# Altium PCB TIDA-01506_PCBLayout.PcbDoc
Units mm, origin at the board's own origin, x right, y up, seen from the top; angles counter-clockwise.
Board outline 40 x 20 mm, 2 copper layers (Top Layer, Bottom Layer), stack 1.575 mm thick; 34 components, 16 nets, 81 pads, 25 vias.
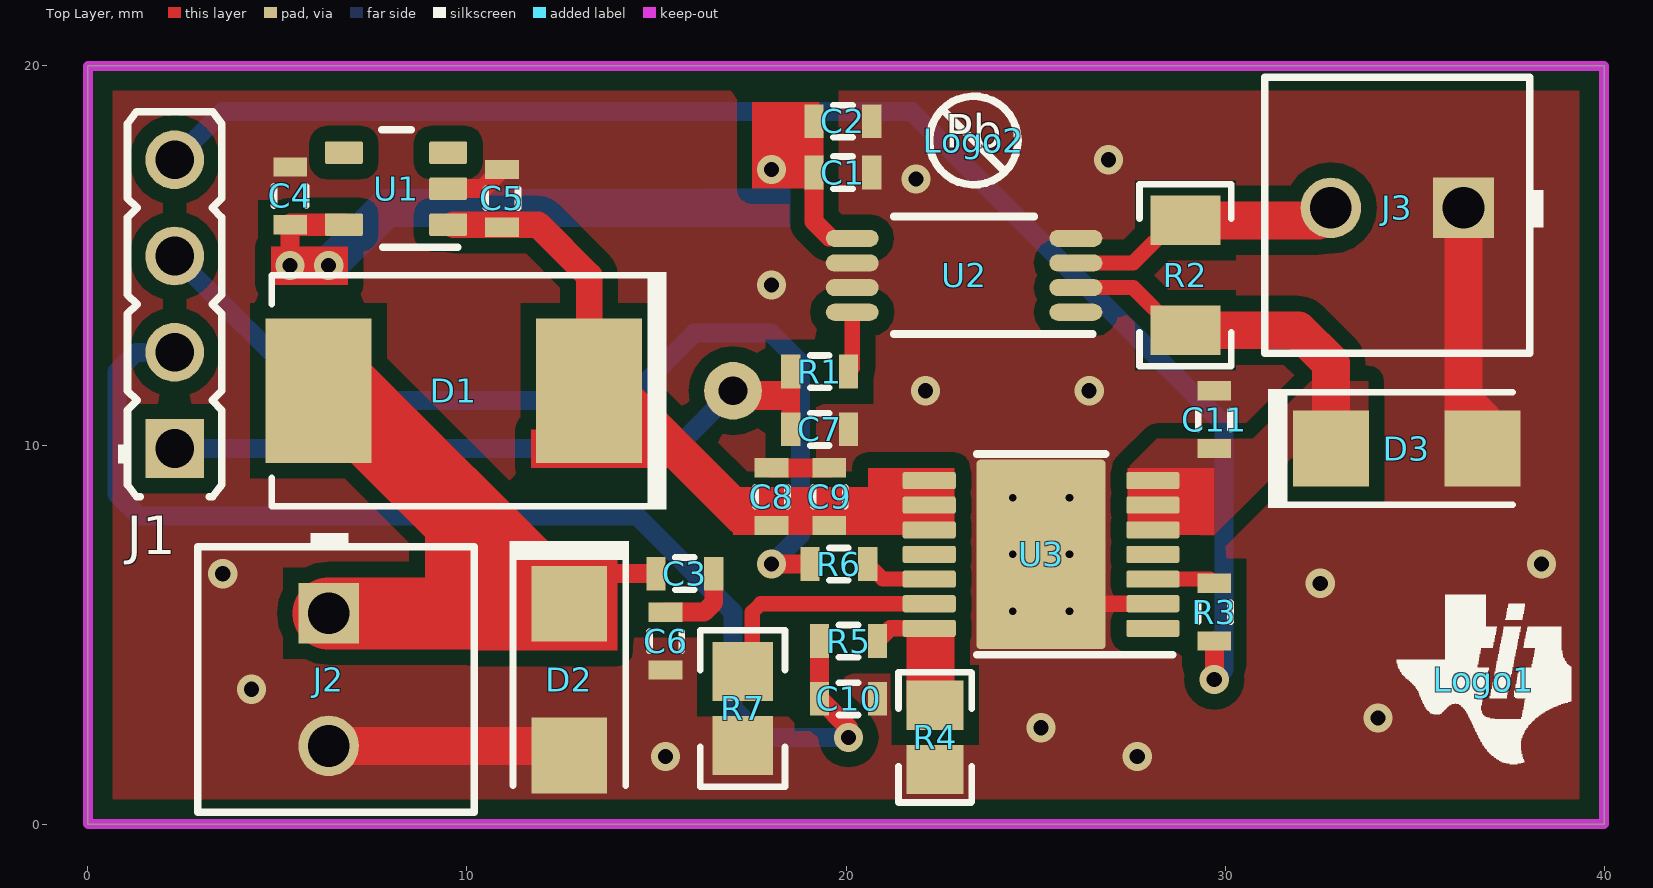
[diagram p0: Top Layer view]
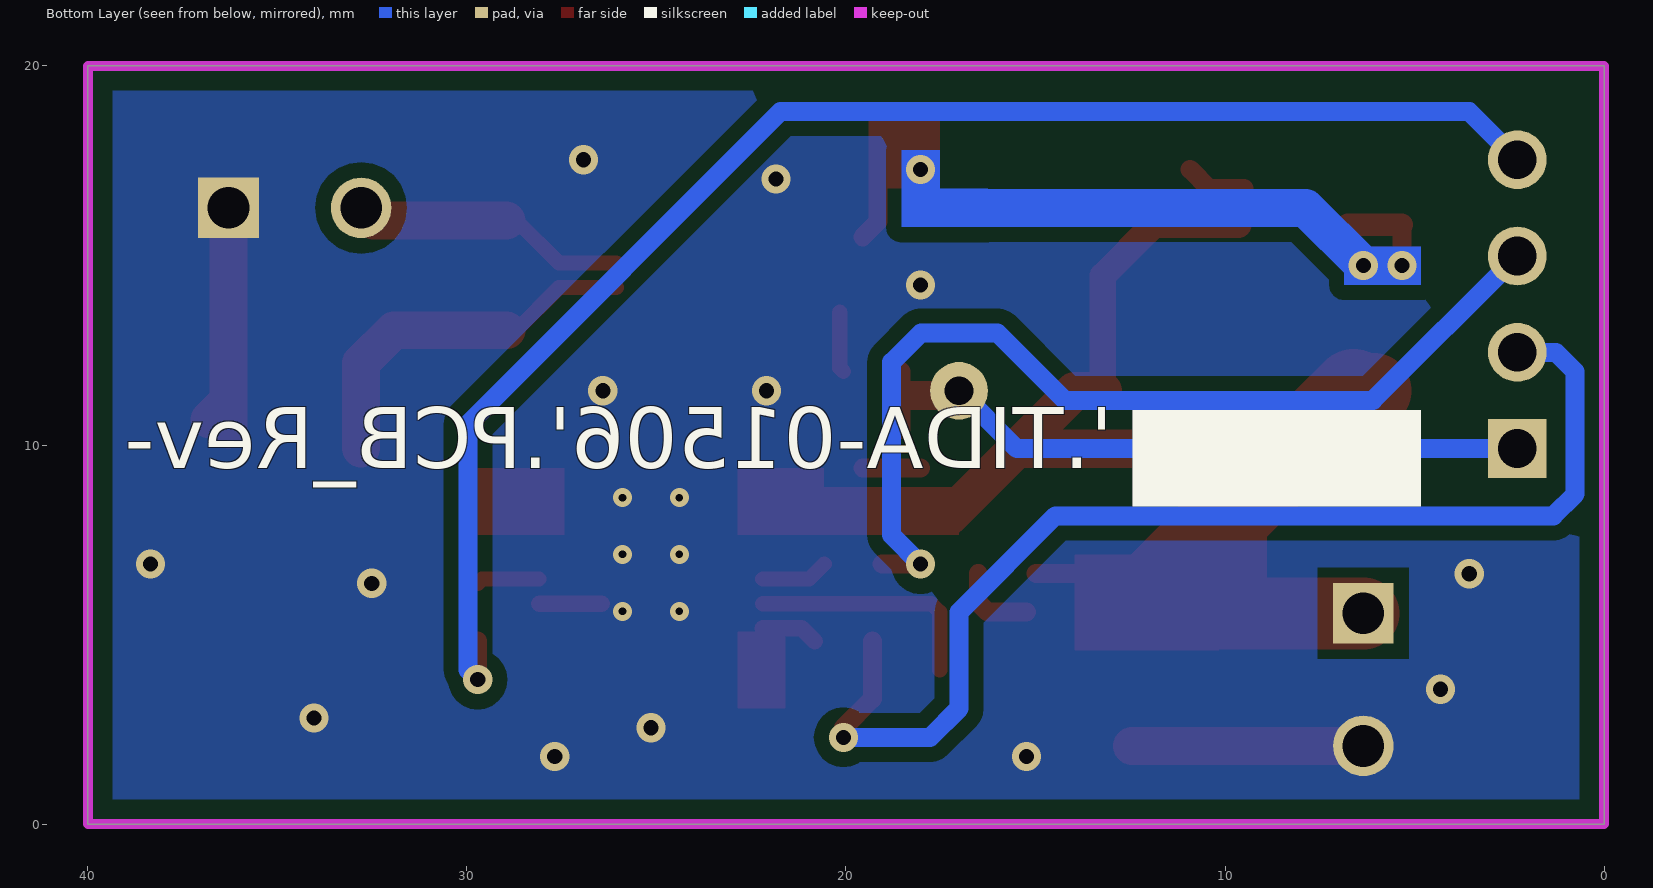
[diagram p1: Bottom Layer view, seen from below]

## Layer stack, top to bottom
Top Solder: solder mask 0.0102, Solder Resist, Dk 3.5
Top Layer: signal copper 0.0356
Dielectric1: core 1.5037, FR-4, Dk 4.8
Bottom Layer: signal copper 0.0356
Bottom Solder: solder mask 0.0102, Solder Resist, Dk 3.5

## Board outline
0,0 40,0 40,20 0,20

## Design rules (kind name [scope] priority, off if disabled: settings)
AcuteAngle [All] p1: minimum=4.50000000000000E+0001 checktracksonly=FALSE
AssemblyTestPointUsage [All] p1: valid=2
BoardOutlineClearance BoardOutlineClearance_MountingHoles [OnCopper and InComponentClass('Mounting Holes')] p1: gap=1.016 ignorepadtopadclearanceinfootprint=FALSE
BoardOutlineClearance BoardOutlineClearance_Poly [OnCopper and IsPoly] p2: gap=0.635 ignorepadtopadclearanceinfootprint=FALSE
BoardOutlineClearance [OnCopper and Not InComponentClass('Logo') and not InComponentClass('FiducialMark') and not InRegion(1000,500,4000,800) and not InPoly] p3: gap=0 ignorepadtopadclearanceinfootprint=FALSE
Clearance Clearance_Keepouts [((IsTrack Or IsArc) And Not InPoly) And IsFree and IsKeepOut vs ((IsTrack Or IsArc) And Not InPoly) And IsFree and IsKeepOut] p1: gap=0 ignorepadtopadclearanceinfootprint=FALSE
Clearance Clearance_Poly [InPolygon] p2: gap=0.4 ignorepadtopadclearanceinfootprint=FALSE except(0: Arc-Hole Track-Hole SMDPad-Hole THPad-Hole Via-Hole Fill-Hole Poly-Hole Region-Hole Text-Hole)
Clearance [All] p3: gap=0.2 ignorepadtopadclearanceinfootprint=FALSE except(0: Arc-Hole Track-Hole SMDPad-Hole THPad-Hole Via-Hole Fill-Hole Poly-Hole Region-Hole Text-Hole)
ComponentClearance ComponentClearance_MountingHoles_FiducialMarks [InComponentClass('Mounting Holes') vs InComponentClass('FiducialMark')] p1: gap=1.27 collisioncheckmode=3 verticalgap=0.254 showdistances=FALSE
ComponentClearance ComponentClearance_Shunt [InComponentClass('Header') vs InComponentClass('Shunt')] p2: gap=0 collisioncheckmode=3 verticalgap=0 showdistances=FALSE
ComponentClearance ComponentClearance_Logo [InComponentClass('Logo')] p3: gap=1.27 collisioncheckmode=3 verticalgap=0.254 showdistances=FALSE
ComponentClearance ComponentClearance_ScrewToNut [(HasFootprint('NY PMS 440 0025 PH')) vs (HasFootprint('Keystone_1902C'))] p4: gap=0.127 collisioncheckmode=3 verticalgap=0.254 showdistances=FALSE
ComponentClearance ComponentClearance_MountingHoles [InComponentClass('Mounting Holes')] p5: gap=6.35 collisioncheckmode=3 verticalgap=2540 showdistances=FALSE
ComponentClearance ComponentClearance_SmallPassives [HasFootprint('0201*') or HasFootprint('0402*') or HasFootprint('0508') or HasFootprint('0603*') or HasFootprint('0612') or HasFootprint('0805*') or HasFootprint('0815*') or HasFootprint('0830*') or HasFootprint('1206*') or HasFootprint('1210*') or HasFootprint('1808*') or HasFootprint('1812*') or HasFootprint('1825*') or HasFootprint('2010*') or HasFootprint('2220*') or HasFootprint('2225*') or HasFootprint('2512*') or HasFootprint('2728*') or HasFootprint('3518*') vs HasFootprint('0201*') or HasFootprint('0402*') or HasFootprint('0508') or HasFootprint('0603*') or HasFootprint('0612') or HasFootprint('0805*') or HasFootprint('0815*') or HasFootprint('0830*') or HasFootprint('1206*') or HasFootprint('1210*') or HasFootprint('1808*') or HasFootprint('1812*') or HasFootprint('1825*') or HasFootprint('2010*') or HasFootprint('2220*') or HasFootprint('2225*') or HasFootprint('2512*') or HasFootprint('2728*') or HasFootprint('3518*')] p6: gap=0.38 collisioncheckmode=3 verticalgap=0.254 showdistances=FALSE
ComponentClearance ComponentClearance_THtoSMT [IsThruComponent vs IsSMTComponent] p7: gap=1.016 collisioncheckmode=3 verticalgap=0.762 showdistances=FALSE
ComponentClearance ComponentClearance_THtoTH [IsThruComponent vs IsThruComponent] p8: gap=0.762 collisioncheckmode=3 verticalgap=0.762 showdistances=FALSE
ComponentClearance [All] p9: gap=0.762 collisioncheckmode=3 verticalgap=0.254 showdistances=FALSE
DiffPairsRouting [All] p1: maxlimit=2.54 minlimit=0.254 mostfreqgap=0.254 toplayer_minwidth=0.381 toplayer_maxwidth=0.381 toplayer_prefwidth=0.381 bottomlayer_minwidth=0.381 bottomlayer_maxwidth=0.381 bottomlayer_prefwidth=0.381 maxuncoupledlength=25.4
FabricationTestPointUsage TestPointUsage [All] p1: valid=2 allowmultiple=FALSE
FabricationTestpoint Testpoint [All] p1: side=3 testpointundercomponent=TRUE minsize=1.016 maxsize=2.54 preferedsize=1.524 minholesize=0 maxholesize=1.016 preferedholesize=0.813 testpointgrid=0.025 allowsidetop=TRUE allowsidebottom=TRUE usegrid=TRUE gridtolerance=0
FanoutControl Fanout_LCC [IsLCC] p1: bgadir=Out bgaviamode=Centered fanoutstyle=Auto fanoutdirection=Alternating viagrid=0.025 // Fanout_LCC (Default Rule)
FanoutControl Fanout_BGA [IsBGA] p2: bgadir=Out bgaviamode=Centered fanoutstyle=Auto fanoutdirection=Alternating viagrid=0.025 // Fanout_BGA (Default Rule)
FanoutControl Fanout_Default [All] p4: bgadir=Out bgaviamode=Centered fanoutstyle=Auto fanoutdirection=Alternating viagrid=0.025 // Fanout_Default (Default Rule)
FanoutControl Fanout_Small [(CompPinCount < 5)] p5: bgadir=Out bgaviamode=Centered fanoutstyle=Auto fanoutdirection=OutThenIn viagrid=0.025 // Fanout_Small (Default Rule)
HoleSize [All] p1: absolutevalues=TRUE maxlimit=6.375 minlimit=0.2 maxpercent=80.000 minpercent=20.000
MinimumAnnularRing MinimumAnnularRing_ThermalPadVias [IsVia and InAnyComponent] p1: minimumring=0
MinimumAnnularRing [All] p2: minimumring=0
MinimumSolderMaskSliver MinimumSolderMaskSliver_Logo [InComponentClass('Logo') vs InComponentClass('Logo')] p1: minsoldermaskwidth=0.018
MinimumSolderMaskSliver [All] p2: minsoldermaskwidth=0.1
PlaneConnect [All] p1: planeconnectstyle=Relief reliefexpansion=0.254 reliefentries=4 reliefconductorwidth=0.254 reliefairgap=0.254
PolygonConnect [All] p1: connectstyle=Direct reliefconductorwidth=0.254 reliefentries=4 polygonreliefangle="90 Angle" airgapwidth=0.254
RoutingVias ThermalPadVias [IsVia and InAnyComponent] p1: holewidth=0.2 width=0.5 viastyle="Through Hole" minholewidth=0.2 minwidth=0.5 maxholewidth=0.33 maxwidth=0.6
RoutingVias [All] p2: holewidth=0.406 width=0.864 viastyle="Through Hole" minholewidth=0.2 minwidth=0.66 maxholewidth=1.016 maxwidth=1.651
SilkToBoardRegionClearance [Not ((IsComment or IsDesignator) And (Hide <> 'False')) and not InRegion(1000,500,4000,800)] p1:
SilkToSilkClearance SilkToSilkClearance_Pb-FreeLogo [(HasFootprint('Pb-Free_Overlay_Medium') OR HasFootprint('Pb-Free_Overlay_Small')) vs (HasFootprint('Pb-Free_Overlay_Medium') OR HasFootprint('Pb-Free_Overlay_Small'))] p1: silktosilkclearance=0
SilkToSilkClearance [All] p2: silktosilkclearance=0
SilkToSolderMaskClearance SilkToComponentPadClearance [(IsPad or IsFill or IsRegion) and InAnycomponent] p1: minsilkscreentomaskgap=0 clearancetoexposedcopper=TRUE
SilkToSolderMaskClearance "Silk to Solder Mask Opening" [All] p2: minsilkscreentomaskgap=0 clearancetoexposedcopper=FALSE
SolderMaskExpansion [All] p1: expansion=0.05
Width [All] p1: maxlimit=2.54 minlimit=0.152 preferedwidth=0.254 checkconnectedcopper=TRUE
15 further rules are at their usual default settings.

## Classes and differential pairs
component class Header: J1
component class TIDA-01506_Schematics: C1 C2 C3 C4 C5 C6 C7 C8 C9 C10 C11 D1 D2 D3 D4 J1 J2 J3 R1 R2 R3 R4 R5 R6 R7 U1 U2 U3
component class AssemblyNote: ZZ1 ZZ2 ZZ3 ZZ4
component class EVM_Hardware: Logo1 Logo2 Logo3 ZZ1 ZZ2 ZZ3 ZZ4
component class Logo: Logo1

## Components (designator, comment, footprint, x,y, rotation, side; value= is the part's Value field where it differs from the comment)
C1 "0603YC104JAT2A" 0603S 19.92,17.189 r180 top value=0.1uF
C2 "CGA3E1X7R1V105K080AC" 0603S 19.92,18.542 r180 top value=1uF
C3 "GRM188R72A104KA35J" 0603S 15.748,6.604 r0 top value=0.1uF
C4 "GRM188Z71C225KE43" 0603S 5.334,16.57 r90 top value=2.2uF
C5 "CGA3E1X7R1V105K080AC" 0603S 10.922,16.51 r270 top value=1uF
C6 "GRM188R72A104KA35J" 0603S 15.24,4.826 r270 top value=0.1uF
C7 "0603YC104JAT2A" 0603S 19.304,10.414 r0 top value=0.1uF
C8 "0603YC104JAT2A" 0603S 18.034,8.636 r270 top value=0.1uF
C9 "CGA3E1X7R1V105K080AC" 0603S 19.558,8.636 r270 top value=1uF
C10 "CGA3E1X7R1V105K080AC" 0603S 20.066,3.302 r0 top value=1uF
C11 "CGA3E1X7R1V105K080AC" 0603S 29.718,10.668 r270 top value=1uF
D1 "B540C-13-F" SMC 9.652,11.43 r180 top value=40V
D2 "SM4T23AY" SMA 12.7,3.81 r270 top value=20V
D3 "B120-13-F" SMA 34.798,9.906 r0 top value=20V
J1 "0022284043" Molex_0022284043 2.286,13.716 r90 top
J2 "39357-0002" Molex_39357-0002 6.35,3.81 r270 top
J3 "39357-0002" Molex_39357-0002 34.544,16.256 r180 top
Logo1 "Texas Instruments" TI_Symbol_Overlay_Small 36.83,3.81 r0 top
Logo2 "Pb-Free Symbol" Pb-Free_Overlay_Small 23.368,18.034 r0 top
Logo3 "FCC disclaimer" FCC_disclaimer 59.69,85.852 r0 top
R1 "FC0603E50R0BTBST1" 0603S 19.304,11.938 r180 top value=50
R2 "UR73V2BTTDR100F" 1206 28.956,14.478 r270 top value=0.1
R3 "CRCW060310K0JNEA" 0603S 29.718,5.588 r270 top value=10k
R4 "CRCW0805750RJNEA" 0805 22.352,2.286 r270 top value=750
R5 "CRCW060310K0JNEA" 0603S 20.066,4.826 r0 top value=10k
R6 "CRCW060310K0JNEA" 0603S 19.812,6.858 r0 top value=10k
R7 "CRCW08051K00FKEA" 0805M 17.272,3.048 r90 top value=1.00k
U1 "TPS70950QDBVRQ1" DBV0005A_N 8.128,16.764 r180 top
U2 "INA240A1QPWRQ1" PW0008A_N 23.114,14.478 r180 top
U3 "TPS1H100AQPWPRQ1" PWP0014F_N 25.146,7.112 r180 top
ZZ1 "This Assembly Note is for PCB labels only" AssemblyNoteLabel 4.699,100.025 r0 top
ZZ2 "These assemblies are ESD sensitive, ESD precautions shall be observed." AssemblyNote 4.699,97.259 r0 top
ZZ3 "These assemblies must be clean and free from flux and all contaminants. Use of no clean flux is not acceptable." AssemblyNote 4.699,95.01 r0 top
ZZ4 "These assemblies must comply with workmanship standards IPC-A-610 Class 2, unless otherwise specified." AssemblyNote 4.699,92.761 r0 top

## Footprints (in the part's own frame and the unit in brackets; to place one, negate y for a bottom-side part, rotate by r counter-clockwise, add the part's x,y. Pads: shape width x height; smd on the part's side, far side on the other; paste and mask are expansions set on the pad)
0603S [mil]
  rect 20x35 smd: 1(-30,0) 2(30,0)
  silkscreen extent -10,-17 10,17, body extent -34,-19 34,19, height 39
0805 [mm] "0805 from SM-752 data"
  rect 1.3x1.5 smd: 1(-0.85,0) 2(0.85,0)
  silkscreen extent -1.72,-0.97 1.72,0.97, body extent -1.1,-0.72 1.1,0.72, height 1.45
0805M [mm] "0805 from SM-752 data"
  rect 1.55x1.6 smd: 1(-0.975,0) 2(0.975,0)
  silkscreen extent -2.07,-1.12 2.07,1.12, body extent -1.1,-0.72 1.1,0.72, height 1.45
1206 [mm] "1206 from SM-752 data"
  rect 1.3x1.85 smd: 1(-1.45,0) 2(1.45,0)
  silkscreen extent -2.4,-1.21 2.4,1.21, body extent -1.7,-0.9 1.7,0.9, height 1.35
AssemblyNote [mm] "Assembly Note"
AssemblyNoteLabel [mm] "Assembly Note for PCB Labels"
DBV0005A_N [mm] "SOT23, 5-Leads, Body 2.9x1.6mm, Pitch 0.95mm, Lead Span 2.8mm, IPC Medium Density"
  rrect17% 1x0.6 smd: 1(-1.375,0.95) 2(-1.375,0) 3(-1.375,-0.95) 4(1.375,-0.95) 5(1.375,0.95)
  silkscreen extent -1.63,-1.55 0.38,1.55, body extent -1.42,-1.46 1.42,1.46, height 1.09
FCC_disclaimer [mm]
Molex_39357-0002 [mm] "Terminal Block, 3.5 mm, 2x1, TH"
  rect 1.6x1.6 hole 1.1: 1(-1.75,0)
  round 1.6 hole 1.1: 2(1.75,0)
  silkscreen extent -3.86,-3.45 3.5,3.84, body extent -3.55,-3.45 3.56,3.84, height 8.51
Molex_0022284043 [mm] "Header, 2.54mm, 4x1, TH"
  rect 1.55x1.55 hole 1.02: 1(-3.81,0)
  round 1.55 hole 1.02: 2(-1.27,0) 3(1.27,0) 4(3.81,0)
  silkscreen extent -5.08,-1.24 5.08,1.5, body extent -5.08,-1.24 5.08,1.24, height 8.4
Pb-Free_Overlay_Small [mm]
  silkscreen extent -1.16,-1.17 1.17,1.17
PW0008A_N [mm] "TSOP, 8-Leads, Body 3x4.4mm, Pitch 0.65mm, IPC Medium Density"
  oval 1.4x0.45 smd: 1(-2.95,0.975) 2(-2.95,0.325) 3(-2.95,-0.325) 4(-2.95,-0.975) 5(2.95,-0.975) 6(2.95,-0.325) 7(2.95,0.325) 8(2.95,0.975)
  silkscreen extent -3.4,-1.55 1.85,1.55, body extent -3.21,-1.5 3.21,1.5, height 1.2
PWP0014F_N [mm] "TSOP, 14-Leads, Body 5x4.4mm, Pitch 0.65mm, Thermal Pad 3x3 mm, IPC Medium Density"
  rrect22% 1.4x0.45 smd: 1(-2.95,1.95) 2(-2.95,1.3) 3(-2.95,0.65) 4(-2.95,0) 5(-2.95,-0.65) 6(-2.95,-1.3) 7(-2.95,-1.95) 8(2.95,-1.95) 9(2.95,-1.3) 10(2.95,-0.65) 11(2.95,0) 12(2.95,0.65) 13(2.95,1.3) 14(2.95,1.95)
  rrect6% 3.4x5 smd paste-2 mask-2: 15(0,0)
  rrect4% 2.31x2.46 on Top Paste: 15(0,0)
  rrect4% 2.31x2.46 on Top Solder: 15(0,0)
  silkscreen extent -3.47,-2.65 1.7,2.65, body extent -3.21,-2.5 3.21,2.5, height 1
SMA [mm] "Molded Diode, 2-Leads, Body 4.3x2.6mm, IPC Medium Density, based on OnSemi component dimensions and land pattern"
  rect 2x2 smd: 1(-2,0) 2(2,0)
  silkscreen extent -3.66,-1.57 2.79,1.57, body extent -2.6,-1.3 2.6,1.3, height 2.42
SMC [mil] "Molded Diode, 2-Leads, Body 6.9x5.8mm, IPC Medium Density, based on OnSemi component dimensions and land patterns"
  rect 110x150 smd: 1(-140.49,0) 2(140.49,0)
  silkscreen extent -221,-124 189,123, body extent -156,-116 156,116, height 91
TI_Symbol_Overlay_Small [mm]
  silkscreen extent -2.3,-2.23 2.3,2.24

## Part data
C1 C7 C8: "CAP, CERM, 0.1 µF, 16 V, +/- 5%, X7R, 0603", Cap_Case=0603, Manufacturer=AVX, Supplier Part Number 1=478-3726-1-ND, TempCo=X7R, Tolerance_%=5, Value1="0.039 ohm", Value2=16V, ValueDisplayed=0.1µF
C2 C9 C10 C11: "CAP, CERM, 1 µF, 35 V, +/- 10%, X7R, AEC-Q200 Grade 1, 0603", Cap_Case=0603, Manufacturer=TDK, Supplier Part Number 1=445-174215-1-ND, TempCo=X7R, Tolerance_%=10, Value1="0.005522 ohm", Value2=35V, ValueDisplayed=22nf
C3 C6: "CAP, CERM, 0.1 µF, 100 V, +/- 10%, X7R, 0603", Cap_Case=0603, Manufacturer=MuRata, Supplier Part Number 1=490-6439-1-ND, TempCo=X7R, Tolerance_%=10, Value1=Unknown, Value2=100V, ValueDisplayed=0.1µF
C4: "CAP, CERM, 2.2 µF, 16 V, +/- 10%, X7R, 0603", Cap_Case=0603, Manufacturer=MuRata, Supplier Part Number 1=81-GRM188Z71C225KE3D, TempCo=X7R, Tolerance_%=10, Value1=Unknown, Value2=16V, ValueDisplayed=2.2µF
C5: "CAP, CERM, 1 µF, 35 V, +/- 10%, X7R, AEC-Q200 Grade 1, 0603", Cap_Case=0603, Manufacturer=TDK, Supplier Part Number 1=445-174215-1-ND, TempCo=X7R, Tolerance_%=10, Value1="0.005522 ohm", Value2=35V, ValueDisplayed=1µF
D1: "Diode, Schottky, 40 V, 5 A, SMC", Manufacturer="Diodes Inc.", Supplier Part Number 1=B540C-FDICT-ND, Value1=5A, Value2=0.55V
D2: library part CMP-0078853-1, "Diode, TVS, Uni, 20 V, 42.8 Vc, AEC-Q101, SMA", Manufacturer=STMicroelectronics, Supplier Part Number 1=497-10912-2-ND
D3: "Diode, Schottky, 20 V, 1 A, SMA", Manufacturer="Diodes Inc.", Supplier Part Number 1=B120-FDICT-ND, Value1=1A, Value2=0.5V
J1: "Header, 2.54mm, 4x1, Tin, TH", Color=Black, Current_A=4, Manufacturer=Molex, Supplier Part Number 1=WM50016-04-ND, Voltage_V=250
J2 J3: "Terminal Block, 3.5 mm, 2x1, Tin, TH", Manufacturer=Molex, Supplier Part Number 1=WM7877-ND
Logo1: library part TI_Logo, "Texas Instrument Corporate Signature"
Logo2: library part Pb-Free
Logo3: library part FCC_disclaimer, "FCC_disclaimer"
R1: "RES, 50, 0.1%, 0.125 W, 0603", Manufacturer="Vishay Thin Film", Power_W=0.125, Supplier Part Number 1=FC0603-50BFCT-ND, TempCo="25 ppm/C", Tolerance_%=0.1, Value1=0.1%, Value2=0.125W, Value_Code=50R0, ValueDisplayed=50
R2: library part CMP-0074897-1, "RES, 0.1, 1%, 0.5 W, AEC-Q200 Grade 1, 1206", Manufacturer="KOA Speer", Power_W=500mW, Supplier Part Number 1=660-UR73V2BTTDR100F, TempCo="100 ppm/C", Tolerance_%=1%, Value2=0.5W, Value_Code=R100, ValueDisplayed=0.1
R3 R5 R6: "RES, 10 k, 5%, 0.1 W, 0603", Manufacturer=Vishay-Dale, Power_W=0.1, Supplier Part Number 1=541-10KGCT-ND, TempCo="200 ppm/C", Tolerance_%=5, Value1=5%, Value2=0.1W, Value_Code=10k0, ValueDisplayed=10k
R4: "RES, 750, 5%, 0.125 W, 0805", Manufacturer=Vishay-Dale, Power_W=0.125, Supplier Part Number 1=541-750ACT-ND, TempCo="200 ppm/C", Tolerance_%=5, Value1=5%, Value2=0.125W, Value_Code=750R, ValueDisplayed=750
R7: "RES, 1.00 k, 1%, 0.125 W, 0805", Manufacturer=Vishay-Dale, Power_W=0.125, Supplier Part Number 1=541-1.00KCCT-ND, TempCo="100 ppm/C", Tolerance_%=1, Value1=1%, Value2=0.125W, Value_Code=1k00, ValueDisplayed=1.00k
U1: library part CMP-0079136-1, "150-mA, 30-V, Ultra-Low IQ, Wide Input LDO with Reverse Current Protection for Automotive, DBV0005A (SOT-23-5)", Alternate Manufacturer="Texas Instruments"
U2: library part CMP-0077375-1, "Automotive, Wide Common-Mode Range, High- and Low-Side, Bidirectional, Zero-Drift, Current-Sense Amplifier With Enhanced PWM Rejection, PW0008A (TSSOP-8)", Alternate Manufacturer="Texas Instruments"
U3: "40V/100mOhm Single Channel Smart High Side Switch, PWP0014F (TSSOP-14)", Alternate Manufacturer="Texas Instruments"
ZZ1: library part AssemblyNoteLabel
ZZ2 ZZ3 ZZ4: library part AssemblyNote

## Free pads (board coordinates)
  round 1.524 hole 0.762: 2(17.018,11.43)

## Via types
v1: diameter 0.77, hole 0.4, Top Layer to Bottom Layer, 19 vias
v2: diameter 0.5, hole 0.2, Top Layer to Bottom Layer, tented both sides, 4 vias
v3: diameter 0.5, hole 0.2, Top Layer to Bottom Layer, 2 vias

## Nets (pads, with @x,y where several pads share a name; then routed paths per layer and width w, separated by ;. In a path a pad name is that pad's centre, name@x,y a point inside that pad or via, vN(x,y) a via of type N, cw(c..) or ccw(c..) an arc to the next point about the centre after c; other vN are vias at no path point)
5V: C1.2 C2.2 C4.1 U1.5 U2.5 | length 16.8
  Top Layer w0.5: v1(5.334,14.732) C4.1 C4.1@5.34,15.814 ; C2.2 C1.2 19.158,15.894 U2.5@19.558,15.494
  Top Layer w0.6: C4.1@5.34,15.814 U1.5
  Bottom Layer w1: v1(6.35,14.732) 7.874,16.256 16.764,16.256
  other v1: 18.034,17.272
12V: C3.1 D1.2 D2.1 J2.1 | length 15.8
  Top Layer w0.5: D2.1@13.494,6.604 C3.1
  Top Layer w1.9: J2.1 11.684,5.56
  Top Layer w2: D1.2 D1.2@6.604,11.43
  Top Layer w2.2: D1.2@6.604,11.43 12.224,5.81 D2.1
GND: C1.1 C2.1 C4.2 C5.1 C6.2 C7.2 C8.1 C9.1 C10.2 C11.1 D2.2 D3.2 J2.2 J3.1 R4.2 R7.1 U1.2 U2.4 U2.6 U2.7 U3.2 U3.15@25.146,7.112 | length 17.5
  Top Layer w0.44: U3.15@26.446,5.812 U3.2
  Top Layer w0.5: U1.2 10.414,16.764 C5.1 ; C8.1 C9.1
  Top Layer w1: J2.2 D2.2@12.45,2.06 ; D3.2@36.294,10.41 J3.1 ; 36.294,11.172 D3.2@36.798,10.668
  other v1: 15.24,1.778 27.686,1.778 25.146,2.54 34.036,2.794 4.318,3.556 32.512,6.35 3.556,6.604 38.354,6.858 22.098,11.43 26.416,11.43 18.034,14.224 21.844,17.018 26.924,17.526
  other v2: 24.396,5.612 25.896,5.612 24.396,8.612 25.896,8.612
  other v3: 24.396,7.112 25.896,7.112
INAOUTTOMCU2.4: C7.1 J1.1 pad.2 R1.2 | length 17.1
  Top Layer w0.5: C7.1@18.542,10.668 C7.1 R1.2
  Bottom Layer w0.5: J1.1 15.494,9.906 pad.2
NetC3_2: C3.2 C6.1 | length 2.1
  Top Layer w0.5: C6.1 16.256,5.588 16.51,5.842 C3.2
NetR1_1: R1.1 U2.8 | length 1.6
  Top Layer w0.4: R1.1 20.164,12.036 U2.8
NetR3_1: R3.1 U3.3 | length 1.7
  Top Layer w0.4: U3.3 29.606,6.462 R3.1
NetR4_1: R4.1 R5.2 U3.14 | length 1.5
  Top Layer w0.44: R5.2 21.164,5.162 U3.14
NetR6_2: R6.2 U3.12 | length 1.8
  Top Layer w0.4: R6.2 20.97,6.462 U3.12
NetR7_2: R7.2 U3.13 | length 6.3
  Top Layer w0.4: R7.2@17.526,4.064 17.526,5.588 17.75,5.812 U3.13
OUT_SWITCH: C11.2 D3.1 R2.2 U2.2 U3.5 U3.6 U3.7 | length 9.6
  Top Layer w0.4: U2.2 27.577,14.153 R2.2@28.702,13.028
  Top Layer w1: R2.2 31.93,13.028 32.798,12.16 D3.1
P2.5_PWM: J1.4 R3.2 | length 39.5
  Top Layer w0.5: v1(29.718,3.81) R3.2
  Bottom Layer w0.5: J1.4 3.556,18.796 21.73,18.796 29.972,10.554 29.972,4.064 v1(29.718,3.81)
P2.6_HS_SWITCH_CS: C10.1 J1.2 R5.1 | length 31.3
  Top Layer w0.5: R5.1 C10.1 20.066,2.54 v1(20.066,2.286)
  Bottom Layer w0.5: J1.2 1.27,12.446 0.762,11.938 0.762,8.705 1.337,8.13 14.476,8.13 17.018,5.588 17.018,3.048 17.78,2.286 v1(20.066,2.286) v1@20.066,2.25
P8.1_DIAG_EN: J1.3 R6.1 | length 25.8
  Top Layer w0.5: v1(18.034,6.858) R6.1
  Bottom Layer w0.5: J1.3 6.096,11.176 14.224,11.176 16.002,12.954 18.026,12.954 18.796,12.184 18.796,7.62 v1(18.034,6.858)
SOLENOID_1: J3.2 R2.1 U2.3 | length 7.1
  Top Layer w0.4: U2.3 27.577,14.803 R2.1@28.702,15.928
  Top Layer w1: R2.1 32.466,15.928 J3.2
VCC_12V: C5.2 C8.2 C9.2 D1.1 U1.1 U3.8 U3.9 U3.10 | length 12.6
  Top Layer w0.7: U1.1@9.652,15.814 11.872,15.814 13.221,14.465 D1.1
  Top Layer w1.003: D1.1 13.97,11.43 17.272,8.128
pads on no net: U1.3 U1.4 U2.1 U3.1 U3.4 U3.11 U3.15@25.146,7.112

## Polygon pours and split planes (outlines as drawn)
OUT_SWITCH on Top Layer "TOP_LAYER_OUT_SWITCH_P002" (solid, remove dead copper, pour order 2): 27.432,9.398 28.194,10.16 29.218,10.16 30.734,10.16 32.258,11.684 33.782,11.684 33.782,9.652 31.75,9.652 29.718,7.62 29.21,7.62 28.702,7.62
GND on Top Layer "TOP_LAYER_GND_P016" (solid, remove dead copper, pour order 16): 0,20.066 40.132,20.066 40.132,0 0,0
GND on Bottom Layer "BOTTOM_LAYER_GND_P014" (solid, remove dead copper, pour order 14): 0,20.066 40.132,20.066 40.132,0.254 39.878,0 0,0

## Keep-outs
Keep-Out Layer:
  the board outline again, w0.254
  text ".Layer_Name" at 14.656,-21.806 h1.52

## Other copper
Top Layer:
  rectangle net OUT_SWITCH: 27.432,7.62 29.718,9.398
  rectangle net VCC_12V: 20.574,7.62 22.86,9.398
  region net 5V: 19.304,16.764 19.304,19.05 17.526,19.05 17.526,16.764
  rectangle net NetR4_1: 21.59,3.048 22.86,5.08
  rectangle net 12V: 10.16,4.572 13.97,7.112
  rectangle net VCC_12V: 17.018,7.62 20.828,8.89
  rectangle net VCC_12V: 11.684,9.398 15.494,10.414
  region net 5V: 6.858,14.224 6.858,15.24 4.826,15.24 4.826,14.224
  rectangle net 12V: 8.89,5.56 11.176,8.128
  rectangle net INAOUTTOMCU2.4: 17.018,10.922 18.542,11.684
  text ".Layer_Name" at 14.656,-21.806 h1.52
Bottom Layer:
  rectangle net 5V: 16.256,15.748 18.288,16.764
  rectangle net 5V: 17.526,15.748 18.542,17.78
  region net 5V: 6.858,14.224 6.858,15.24 4.826,15.24 4.826,14.224
  text ".Layer_Name" at 14.656,-21.806 h1.52

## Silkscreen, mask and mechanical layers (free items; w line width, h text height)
Top Overlay:
  text ".Layer_Name" at 14.656,-21.806 h1.52
Bottom Overlay:
  region: 12.446,10.922 4.826,10.922 4.826,8.382 12.446,8.382
  text "'.TIDA-01506'.PCB_Rev-" at 12.954,8.865 h2.75
  text ".Layer_Name" at 14.656,-21.806 h1.52
Top Paste:
  text ".Layer_Name" at 14.656,-21.806 h1.52
Bottom Paste:
  text ".Layer_Name" at 14.656,-21.806 h1.52
Top Solder:
  text ".Layer_Name" at 14.656,-21.806 h1.52
  text ".Layer_Name" at 14.656,-21.806 h1.52
Bottom Solder:
  text ".Layer_Name" at 14.656,-21.806 h1.52
Drill Guide:
  text ".Layer_Name" at 14.656,-21.806 h1.52
M1 Board Outline:
  the board outline again, w0.254
  text ".Layer_Name" at 14.656,-21.806 h1.52
M2 Board Dimensions:
  rectangle: 3.175,-10.16 12.7,-6.985
  rectangle: 0,-6.985 3.175,-3.81
  lines w0.178: 0,-6.985 25.4,-6.985 ; 3.175,-10.16 3.175,-3.81 ; 6.35,-10.16 6.35,-3.81 ; 12.7,-10.16 12.7,-3.81 ; 19.05,-10.16 19.05,-3.81 ; 0,-10.16 0,-3.81 25.4,-3.81 25.4,-10.16 0,-10.16
  text ".Layer_Name" at 14.656,-21.806 h1.52
M3 3D STEP Top:
  text ".Layer_Name" at 14.656,-21.806 h1.52
M4 3D STEP Bottom:
  text ".Layer_Name" at 14.656,-21.806 h1.52
M5 Assembly Top:
  lines w0.254: -7.417,-23.626 160.223,-23.626 ; -7.417,-18.462 160.274,-18.462 ; -7.417,-13.297 -7.417,-28.791 94.31,-28.791 160.274,-28.791 160.274,-13.297 -7.404,-13.297 -7.404,-28.791 32.614,-28.791 ; 55.194,-28.791 55.194,-13.297 ; 87.376,-18.462 87.376,-13.297 ; 108.712,-18.462 108.712,-13.297 ; 124.511,-28.956 124.511,-23.804
  text "COMPONENTS MARKED 'DNP' SHOULD NOT BE POPULATED." at 29.299,-8.09 h1.52
  text "ASSEMBLY VARIANT:" at 29.286,-11.024 h1.52
  text ".VariantName" at 55.601,-11.024 h1.52
  text "PCB VIEWED FROM TOP SIDE" at -5.804,-16.654 h1.52
  text "BOARD #:" at 57.099,-16.654 h1.52
  text ".PRJ_Number" at 70.955,-16.654 h1.52
  text "REV:" at 92.405,-16.654 h1.52
  text ".PCB_Rev" at 99.809,-16.654 h1.52
  text "SVN REV:" at 113.69,-16.654 h1.52
  text ".VersionControl_RevNumber" at 126.543,-16.654 h1.52
  text "TID #:" at 57.099,-21.819 h1.52
  text ".TID" at 70.955,-21.819 h1.52
  text "PLOT NAME =" at -5.804,-27.034 h1.52
  text ".plot_File_Name" at 14.656,-27.034 h1.52
  text "GENERATED    :" at 57.15,-27.034 h1.52
  text ".Print_Date" at 79.235,-27.034 h1.52
  text ".Print_Time" at 97.752,-27.034 h1.52
  text "TEXAS INSTRUMENTS" at 129.87,-27.034 h1.52
M6 Assembly Bottom:
  lines w0.254: -7.429,-18.474 160.261,-18.474 ; -7.379,-23.639 160.261,-23.639 ; 28.334,-28.969 28.334,-23.817 ; 44.133,-18.474 44.133,-13.31 ; 65.468,-18.474 65.468,-13.31 ; 97.65,-28.804 97.65,-13.31 ; 120.231,-28.804 160.249,-28.804 160.249,-13.31 -7.429,-13.31 -7.429,-28.804 58.534,-28.804 160.261,-28.804 160.261,-13.31
  text "COMPONENTS MARKED 'DNP' SHOULD NOT BE POPULATED." at 154.991,-8.077 h1.52
  text ".VariantName" at 128.473,-11.024 h1.52
  text "ASSEMBLY VARIANT:" at 154.864,-11.024 h1.52
  text ".VersionControl_RevNumber" at 26.302,-16.667 h1.52
  text "SVN REV:" at 39.154,-16.667 h1.52
  text ".PCB_Rev" at 53.035,-16.667 h1.52
  text "REV:" at 60.439,-16.667 h1.52
  text ".PRJ_Number" at 81.89,-16.667 h1.52
  text "BOARD #:" at 95.745,-16.667 h1.52
  text "PCB VIEWED FROM BOTTOM SIDE" at 158.648,-16.667 h1.52
  text ".TID" at 81.89,-21.831 h1.52
  text "TID #:" at 95.745,-21.831 h1.52
  text "TEXAS INSTRUMENTS" at 22.974,-27.047 h1.52
  text ".Print_Time" at 55.093,-27.047 h1.52
  text ".Print_Date" at 73.609,-27.047 h1.52
  text "GENERATED    :" at 95.694,-27.047 h1.52
  text ".plot_File_Name" at 138.189,-27.047 h1.52
  text "PLOT NAME =" at 158.648,-27.047 h1.52
M9 Title Sheet:
  drawing of 57 lines, arcs and shapes, not listed
  text "1" at 18.792,204.127 h1.78
  text "2" at 82.182,204.127 h1.78
  text "3" at 145.411,204.127 h1.78
  text "4" at 209.08,204.127 h1.78
  text "5" at 272.555,204.127 h1.78
  text "6" at 336.182,204.127 h1.78
  text "A" at -10.579,175.095 h1.78
  text "A" at 365.341,175.095 h1.78
  text "B" at -10.579,114.643 h1.78
  text "B" at 365.341,114.643 h1.78
  text "C" at -10.579,54.318 h1.78
  text "C" at 365.341,54.318 h1.78
  text "PROJECT TITLE:" at 288.125,7.048 h1.14
  text ".PRJ_Title" at 289.395,3.662 h1.78
  text "DESIGNED FOR:" at 288.125,-0.597 h1.14
  text ".PRJ_Customer" at 289.395,-4.153 h1.78
  text "D" at -10.579,-5.88 h1.78
  text "D" at 365.341,-5.88 h1.78
  text "FILE NAME:" at 288.125,-8.217 h1.14
  text ".PCB_File_Name_No_Path" at 289.395,-11.265 h1.78
  text "Texas Instruments (TI) and/or its licensors do not warrant the accuracy or completeness of this specification" at 161.9,-15.376 h1.14
  text "ENGINEER:" at 288.125,-15.583 h1.14
  text "LAYOUT BY:" at 326.352,-15.583 h1.14
  text "or any information contained therein. TI and/or its licensors do not warrant that this design will meet" at 160.757,-18.237 h1.14
  text ".PRJ_Engineer" at 289.395,-19.52 h1.78
  text ".PCB_Layout" at 327.635,-19.52 h1.78
  text "the specifications, will be suitable for your application or fit for any particular purpose, or will operate in" at 160.757,-21.099 h1.14
  text ".Layer_Name" at 14.656,-21.806 h1.52
  text "ALTIUM DESIGNER VERSION:" at 326.352,-23.457 h1.14
  text "an implementation. TI and/or its licensors do not warrant that the design is production worthy. You should" at 160.757,-23.961 h1.14
  text "completely validate and test your design implementation to confirm the system functionality for your application." at 161.9,-26.822 h1.14
  text ".print_Scale" at 289.395,-26.843 h1.78
  text ".Application_BuildNumber" at 327.635,-26.843 h1.78
  text "1" at 18.792,-32.093 h1.78
  text "2" at 82.182,-32.093 h1.78
  text "3" at 145.411,-32.093 h1.78
  text "4" at 209.08,-32.093 h1.78
  text "5" at 272.555,-32.093 h1.78
  text "6" at 336.182,-32.093 h1.78
M10 Fab Notes:
  drawing of 173 lines, arcs and shapes, not listed
  text "DESIGN INFORMATION" at 314.402,157.505 h1.52
  text "MIN. TRACK WIDTH:" at 298.03,152.933 h1.52
  text "8" at 325.874,152.933 h1.52
  text "MIL" at 329.805,152.933 h1.52
  text "MIN. CLEARANCE:" at 298.03,149.581 h1.52
  text "0.2" at 324.35,149.581 h1.52
  text "mm" at 329.805,149.581 h1.52
  text "MIN. VIA PAD SIZE:" at 298.03,146.228 h1.52
  text "24" at 325.113,146.228 h1.52
  text "MIL" at 329.805,146.228 h1.52
  text "0.05mm (2MIL)" at 315.683,142.628 h1.52
  text "MINIMUM ANNULAR RING" at 289.667,142.52 h1.52
  text "EXTERNAL" at 333.666,142.52 h1.52
  text "PER" at 294.747,139.522 h1.52
  text "IPC-D-275 CLASS 2 LEVEL C" at 300.335,139.522 h1.52
  text "MIL, HOLES" at 338.136,136.67 h1.52
  text "+/-" at 328.168,136.652 h1.52
  text "+/-" at 349.86,136.652 h1.52
  text "REGISTRATION TOLERANCES:" at 289.667,136.525 h1.52
  text "METAL" at 320.142,136.525 h1.52
  text "5" at 334.777,136.525 h1.52
  text "3" at 355.935,136.525 h1.52
  text "MIL" at 358.888,136.525 h1.52
  text "+/-" at 349.86,133.655 h1.52
  text "HOLE SIZE TOLERANCE (UNLESS OTHERWISE SPECIFIED):" at 289.667,133.528 h1.52
  text "3" at 355.935,133.528 h1.52
  text "MIL" at 358.888,133.528 h1.52
  text "MATERIAL:" at 287.768,128.208 h1.52
  text "FR-4 High Tg" at 312.824,124.643 h1.52
  text "FR-408" at 298.462,124.425 h1.52
  text "OTHER" at 336.257,124.425 h1.52
  text "X" at 308.889,124.333 h1.52
  text "62 MIL (1.6mm) +/-10%" at 306.592,120.292 h1.52
  text "THICKNESS:" at 289.667,120.184 h1.52
  text "X" at 303.337,120.184 h1.52
  text "OTHER" at 339.229,120.184 h1.52
  text "TOLERANCE:" at 289.667,116.17 h1.52
  text "X" at 310.986,116.17 h1.52
  text "ANSI IPC-6012 TYPE 3 CLASS 2" at 315.734,116.17 h1.52
  text "OTHER +/-" at 315.734,112.208 h1.52
  text "BOW & TWIST:" at 289.667,108.22 h1.52
  text "X" at 310.986,108.22 h1.52
  text "ANSI IPC-6012 TYPE 3 CLASS 2" at 315.734,108.22 h1.52
  text "OTHER +/-" at 315.734,104.194 h1.52
  text "DRILLING:" at 287.768,100.676 h1.52
  text "REFERENCE:" at 289.667,97.705 h1.52
  text "X" at 306.132,97.705 h1.52
  text "AS SHOWN" at 310.882,97.705 h1.52
  text "X" at 329.018,97.705 h1.52
  text "NC_DRILL FILES" at 332.498,97.705 h1.52
  text "PTH COPPER THICKNESS:" at 289.667,93.691 h1.52
  text "X" at 318.375,93.691 h1.52
  text "20-30 um" at 321.855,93.691 h1.52
  text "OTHER" at 340.067,93.691 h1.52
  text "BOARD FINISH:" at 287.768,89.653 h1.52
  text "SILKSCREEN:" at 291.711,86.656 h1.52
  text "X" at 315.81,86.656 h1.52
  text "TOP" at 319.01,86.656 h1.52
  text "X" at 328.764,86.656 h1.52
  text "BOTTOM" at 331.99,86.656 h1.52
  text "SILKSCREEN COLOR:" at 291.711,82.414 h1.52
  text "X" at 315.783,82.414 h1.52
  text "WHITE" at 319.01,82.414 h1.52
  text "OTHER" at 331.99,82.414 h1.52
  text "X" at 319.111,78.37 h1.52
  text "GREEN" at 322.338,78.37 h1.52
  text "OTHER" at 338.035,78.37 h1.52
  text "SOLDER RESIST COLOR:" at 291.711,78.096 h1.52
  text "X" at 319.111,74.052 h1.52
  text "MATTE" at 322.338,74.052 h1.52
  text "SEMI-GLOSS" at 338.023,74.036 h1.52
  text "IMMERSION GOLD (ENIG)" at 314.718,69.264 h1.52
  text "ENEPIG" at 348.691,69.18 h1.52
  text "SURFACE FINISH:" at 287.768,69.155 h1.52
  text "X" at 309.969,69.155 h1.52
  text "IMM. TIN/SILVER OR EQUIV" at 296.139,65.167 h1.52
  text "OTHER" at 332.498,65.167 h1.52
  text "ARRAY/PANEL:" at 287.768,60.621 h1.52
  text "CUT AND TRIM PER M1 BOARD OUTLINE" at 314.718,60.512 h1.52
  text "N.C. ROUTE" at 314.718,56.658 h1.52
  text "X" at 331.964,56.658 h1.52
  text "V. SCORE" at 336.714,56.658 h1.52
  text "CERTIFICATION:" at 287.768,53.178 h1.52
  text "MATERIALS AND WORKMANSHIP FOR ALL PCBS" at 306.183,53.178 h1.52
  text "TO MEET OR EXCEED THE REQUIREMENTS OF:" at 306.183,50.689 h1.52
  text "X" at 296.696,47.222 h1.52
  text "ANSI IPC-A-600F CLASS ->" at 300.227,47.222 h1.52
  text "X" at 341.859,47.222 h1.52
  text "2" at 344.88,47.222 h1.52
  text "1" at 336.879,47.184 h1.52
  text "3" at 353.872,47.184 h1.52
  text "X" at 317.373,43.171 h1.52
  text "RoHS" at 320.852,43.171 h1.52
  text "OTHER" at 337.22,43.171 h1.52
  text "PER ORDER" at 347.305,43.171 h1.52
  text "ALL BOARDS MUST MEET OR EXCEED UL94-V0 REQUIREMENTS." at 288.468,38.964 h1.52
  text "PCB MUST BEAR THE UL94V-0 UL REGISTERED MATERIAL ID NUMBER" at 288.468,35.916 h1.52
  text "ADDITIONAL REQUIREMENTS:" at 287.768,31.512 h1.52
  text "MICROSECTION:" at 289.667,28.591 h1.52
  text "YES" at 312.673,28.591 h1.52
  text "REQUIRED" at 334.555,24.625 h1.52
  text "BARE BOARD ELEC. TEST:" at 289.667,24.553 h1.52
  text "NONE" at 322.833,24.553 h1.52
  text "X" at 331.329,24.553 h1.52
  text "PER ORDER" at 349.592,24.553 h1.52
  text ".Layer_Name" at 14.656,-21.806 h1.52
M11 Gerber Information:
  lines w0.254: -7.417,-23.626 160.223,-23.626 ; -7.417,-18.462 160.274,-18.462 ; -7.417,-13.297 -7.417,-28.791 94.31,-28.791 160.274,-28.791 160.274,-13.297 -7.404,-13.297 -7.404,-28.791 32.614,-28.791 ; 55.194,-28.791 55.194,-13.297 ; 87.376,-18.462 87.376,-13.297 ; 108.712,-18.462 108.712,-13.297 ; 124.511,-28.956 124.511,-23.804
  text "ALL ARTWORK VIEWED FROM TOP SIDE" at -5.804,-16.654 h1.52
  text "BOARD #:" at 57.099,-16.654 h1.52
  text ".PRJ_Number" at 70.955,-16.654 h1.52
  text "REV:" at 92.405,-16.654 h1.52
  text ".PCB_Rev" at 99.809,-16.654 h1.52
  text "SVN REV:" at 113.69,-16.654 h1.52
  text ".VersionControl_RevNumber" at 126.543,-16.654 h1.52
  text "LAYER NAME =" at -5.804,-21.806 h1.52
  text "TID #:" at 57.099,-21.819 h1.52
  text ".TID" at 70.955,-21.819 h1.52
  text "PLOT NAME =" at -5.804,-27.034 h1.52
  text ".plot_File_Name" at 14.656,-27.034 h1.52
  text "GENERATED    :" at 57.15,-27.034 h1.52
  text ".Print_Date" at 79.235,-27.034 h1.52
  text ".Print_Time" at 97.752,-27.034 h1.52
  text "TEXAS INSTRUMENTS" at 129.87,-27.034 h1.52
M12 Stackup:
  drawing of 191 lines, arcs and shapes, not listed
  text "Layer" at 248.675,198.882 h1.52
  text "Name" at 259.086,198.882 h1.52
  text "Material" at 282.702,198.882 h1.52
  text "Thickness" at 304.54,198.882 h1.52
  text "Constant" at 321.046,198.882 h1.52
  text "Board Layer Stack" at 335.52,198.882 h1.52
  text "1" at 248.675,195.834 h1.52
  text "Top Overlay" at 259.086,195.834 h1.52
  text "2" at 248.675,192.786 h1.52
  text "Top Solder" at 259.086,192.786 h1.52
  text "Solder Resist" at 282.702,192.786 h1.52
  text "0.40mil" at 304.54,192.786 h1.52
  text "3.5" at 321.046,192.786 h1.52
  text "3" at 248.675,189.738 h1.52
  text "Top Layer" at 259.086,189.738 h1.52
  text "Copper" at 282.702,189.738 h1.52
  text "1.40mil" at 304.54,189.738 h1.52
  text "4" at 248.675,186.69 h1.52
  text "Dielectric1" at 259.086,186.69 h1.52
  text "FR-4" at 282.702,186.69 h1.52
  text "59.20mil" at 304.54,186.69 h1.52
  text "4.8" at 321.046,186.69 h1.52
  text "5" at 248.675,183.642 h1.52
  text "Bottom Layer" at 259.086,183.642 h1.52
  text "Copper" at 282.702,183.642 h1.52
  text "1.40mil" at 304.54,183.642 h1.52
  text "6" at 248.675,180.594 h1.52
  text "Bottom Solder" at 259.086,180.594 h1.52
  text "Solder Resist" at 282.702,180.594 h1.52
  text "0.40mil" at 304.54,180.594 h1.52
  text "3.5" at 321.046,180.594 h1.52
  text "7" at 248.675,177.546 h1.52
  text "Bottom Overlay" at 259.086,177.546 h1.52
  text ".Layer_Name" at 14.656,-21.806 h1.52
M13 Component Bodies Top:
  text ".Layer_Name" at 14.656,-21.806 h1.52
M14 Component Bodies Bottom:
  text ".Layer_Name" at 14.656,-21.806 h1.52
M15 Courtyards Top:
  text ".Layer_Name" at 14.656,-21.806 h1.52
M16 Courtyards Bottom:
  text ".Layer_Name" at 14.656,-21.806 h1.52
Drill Drawing:
  circle w0.254: c135.862,78.83 r0.562
  lines w0.254: 135.3,73.488 135.581,73.488 135.862,73.207 136.143,73.488 136.424,73.488 136.143,73.769 136.424,74.05 136.143,74.05 135.862,74.331 135.581,74.05 135.3,74.05 135.581,73.769 135.3,73.488 ; 135.3,75.737 136.424,75.737 136.424,76.862 135.3,76.862 135.3,75.737 ; 135.3,80.798 135.862,81.079 136.424,80.798 136.143,81.36 136.424,81.923 135.862,81.641 135.3,81.923 135.581,81.36 135.3,80.798 ; 135.3,84.453 136.424,84.453 135.862,83.328 135.3,84.453
  lines w0.305: 134.264,72.448 213.333,72.448 ; 134.264,85.1 213.333,85.1 ; 142.282,69.917 142.282,87.63 ; 150.338,69.917 150.338,87.63 ; 166.13,69.917 166.13,87.63 ; 172.336,69.917 172.336,87.63 ; 181.489,69.917 181.489,87.63 ; 199.51,69.917 199.51,87.63 ; 134.264,69.917 213.333,69.917 213.333,87.63 134.264,87.63 134.264,69.917
  text "Symbol" at 135.783,85.859 h1.83
  text "Quantity" at 143.041,85.859 h1.83
  text "Finished Hole Size" at 151.097,85.859 h1.83
  text "Plated" at 166.889,85.859 h1.83
  text "Hole Type" at 173.095,85.859 h1.83
  text "Drill Layer Pair" at 182.248,85.859 h1.83
  text "Hole Tolerance" at 200.269,85.859 h1.83
  text "6" at 143.041,83.328 h1.52
  text "7.87mil (0.200mm)" at 151.097,83.328 h1.52
  text "PTH" at 166.889,83.328 h1.52
  text "Round" at 173.095,83.328 h1.52
  text "Top Layer - Bottom Layer" at 182.248,83.328 h1.52
  text "19" at 143.041,80.798 h1.52
  text "15.75mil (0.400mm)" at 151.097,80.798 h1.52
  text "PTH" at 166.889,80.798 h1.52
  text "Round" at 173.095,80.798 h1.52
  text "Top Layer - Bottom Layer" at 182.248,80.798 h1.52
  text "1" at 143.041,78.267 h1.52
  text "30.00mil (0.762mm)" at 151.097,78.267 h1.52
  text "PTH" at 166.889,78.267 h1.52
  text "Round" at 173.095,78.267 h1.52
  text "Top Layer - Bottom Layer" at 182.248,78.267 h1.52
  text "4" at 143.041,75.737 h1.52
  text "40.16mil (1.020mm)" at 151.097,75.737 h1.52
  text "PTH" at 166.889,75.737 h1.52
  text "Round" at 173.095,75.737 h1.52
  text "Top Layer - Bottom Layer" at 182.248,75.737 h1.52
  text "4" at 143.041,73.207 h1.52
  text "43.31mil (1.100mm)" at 151.097,73.207 h1.52
  text "PTH" at 166.889,73.207 h1.52
  text "Round" at 173.095,73.207 h1.52
  text "Top Layer - Bottom Layer" at 182.248,73.207 h1.52
  text "34 Total" at 143.041,70.676 h1.52
  text ".Layer_Name" at 14.656,-21.806 h1.52
M17 Embedded Cavity:
  text ".Layer_Name" at 14.656,-21.806 h1.52
M18 Embedded Assembly:
  text ".Layer_Name" at 14.656,-21.806 h1.52
M19 Embedded Keepout:
  text ".Layer_Name" at 14.656,-21.806 h1.52

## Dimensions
0,0 to 40,0 on M2 Board Dimensions
0,0 to 0,20 on M2 Board Dimensions
0,-10.16 to 25.4,-10.16 on M2 Board Dimensions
